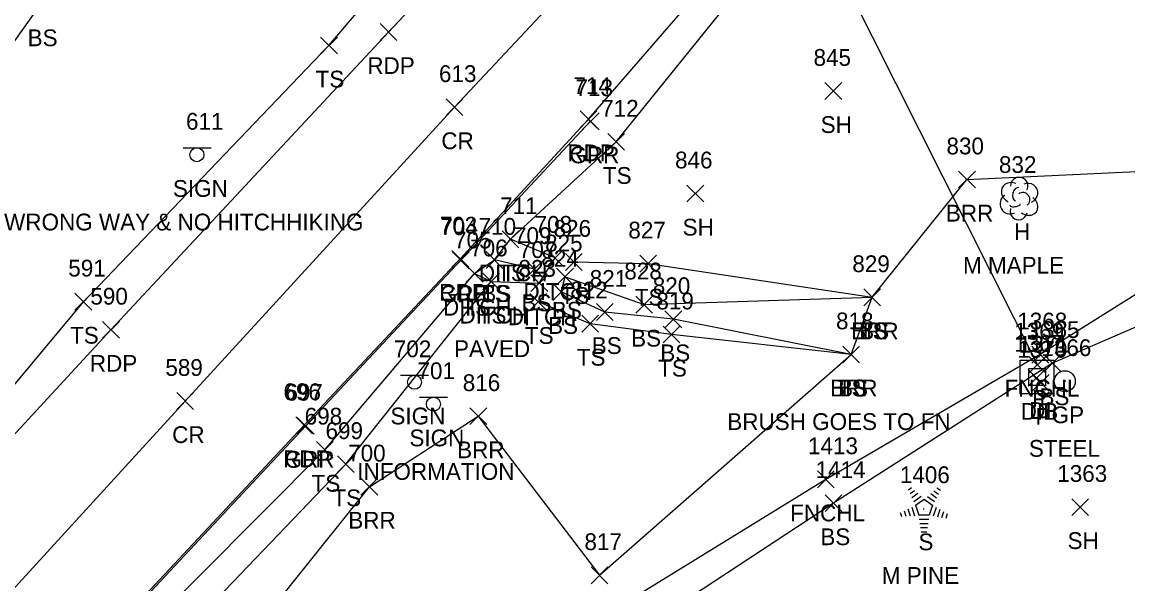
# Model space of a CAD drawing. Extents: x 1688195 to 1692013, y 424605 to 441234.
# Drawn here: x 1691586.4 to 1691718.1, y 439107.6 to 439174.5 of the extents above; entities that cross this region are included whole.
import ezdxf

# ---------------------------------------------------------------- set-up
doc = ezdxf.new("R2010")
doc.units = 0
for name, color, linetype in [('D_A', 7, 'Continuous'), ('D_C', 7, 'Continuous'), ('D_I', 7, 'Continuous'), ('D_TIC', 7, 'Continuous'), ('DCP', 7, 'Continuous'), ('DD', 7, 'Continuous'), ('DS', 7, 'Continuous'), ('L_A', 7, 'Continuous'), ('L_C', 7, 'Continuous'), ('L_I', 7, 'Continuous'), ('L_TIC', 7, 'Continuous'), ('LABL', 7, 'Continuous'), ('LELB', 7, 'Continuous'), ('LFNC', 7, 'Continuous'), ('LTC', 7, 'Continuous'), ('LTD', 7, 'Continuous'), ('P_A', 7, 'Continuous'), ('P_I', 7, 'Continuous'), ('P_TIC', 7, 'Continuous'), ('PET', 7, 'Continuous'), ('PRC', 7, 'Continuous'), ('R_A', 7, 'Continuous'), ('R_C', 7, 'Continuous'), ('R_I', 7, 'Continuous'), ('R_TIC', 7, 'Continuous'), ('RGP', 7, 'Continuous'), ('RGR', 7, 'Continuous'), ('S_A', 7, 'Continuous'), ('S_C', 7, 'Continuous'), ('S_I', 7, 'Continuous'), ('SSGN', 7, 'Continuous')]:
    doc.layers.add(name, color=color, linetype=linetype)

msp = doc.modelspace()

# ---------------------------------------------------------------- linework, layer by layer
at = {"layer": 'D_TIC'}
for points in [[(1691643.54, 439147.64), (1691645.54, 439149.64)], [(1691645.54, 439147.64), (1691643.54, 439149.64)], [(1691648.86, 439145.42), (1691650.86, 439147.42)], [(1691650.86, 439145.42), (1691648.86, 439147.42)], [(1691639.28, 439143.55), (1691641.28, 439145.55)], [(1691641.28, 439143.55), (1691639.28, 439145.55)], [(1691641.24, 439142.61), (1691643.24, 439144.61)], [(1691643.24, 439142.61), (1691641.24, 439144.61)], [(1691646.98, 439142.41), (1691648.98, 439144.41)], [(1691648.98, 439142.41), (1691646.98, 439144.41)], [(1691706.28, 439132.69), (1691708.28, 439134.69)], [(1691708.28, 439132.69), (1691706.28, 439134.69)], [(1691706.2, 439131.14), (1691708.2, 439133.14)], [(1691708.2, 439131.14), (1691706.2, 439133.14)], [(1691706.68, 439130.54), (1691708.68, 439132.54)], [(1691708.68, 439130.54), (1691706.68, 439132.54)]]:
    msp.add_lwpolyline(points, dxfattribs=at)
at = {"layer": 'DCP'}
msp.add_lwpolyline([(1691648.19, 439251.17), (1691707.28, 439133.69)], dxfattribs=at)
at = {"layer": 'DD'}
msp.add_lwpolyline([(1691640.28, 439144.55), (1691642.24, 439143.61), (1691647.98, 439143.41), (1691649.86, 439146.42), (1691644.54, 439148.64)], dxfattribs=at)
at = {"layer": 'DS'}
for p, q in [((1691705.25, 439134.24), (1691709.25, 439134.24)), ((1691705.25, 439130.24), (1691705.25, 439134.24)), ((1691709.25, 439134.24), (1691709.25, 439130.24)), ((1691706.25, 439131.24), (1691706.25, 439133.24)), ((1691706.25, 439133.24), (1691708.25, 439133.24)), ((1691707.26, 439132.24), (1691707.26, 439132.24)), ((1691707.26, 439132.24), (1691707.26, 439132.24)), ((1691708.25, 439133.24), (1691708.25, 439131.24)), ((1691708.25, 439131.24), (1691706.25, 439131.24)), ((1691709.25, 439130.24), (1691705.25, 439130.24))]:
    msp.add_line(p, q, dxfattribs=at)
at = {"layer": 'L_TIC'}
for points in [[(1691621.93, 439170.73), (1691623.93, 439172.73)], [(1691623.93, 439170.73), (1691621.93, 439172.73)], [(1691681.99, 439165.31), (1691683.99, 439167.31)], [(1691683.99, 439165.31), (1691681.99, 439167.31)], [(1691656.14, 439159.25), (1691658.14, 439161.25)], [(1691658.14, 439159.25), (1691656.14, 439161.25)], [(1691697.9, 439154.76), (1691699.9, 439156.76)], [(1691699.9, 439154.76), (1691697.9, 439156.76)], [(1691665.56, 439153.09), (1691667.56, 439155.09)], [(1691667.56, 439153.09), (1691665.56, 439155.09)], [(1691643.54, 439147.64), (1691645.54, 439149.64)], [(1691645.54, 439147.64), (1691643.54, 439149.64)], [(1691641.63, 439145.18), (1691643.63, 439147.18)], [(1691643.63, 439145.18), (1691641.63, 439147.18)], [(1691641.63, 439145.18), (1691643.63, 439147.18)], [(1691643.63, 439145.18), (1691641.63, 439147.18)], [(1691651.1, 439144.94), (1691653.1, 439146.94)], [(1691653.1, 439144.94), (1691651.1, 439146.94)], [(1691659.94, 439144.74), (1691661.94, 439146.74)], [(1691661.94, 439144.74), (1691659.94, 439146.74)], [(1691639.28, 439143.55), (1691641.28, 439145.55)], [(1691641.28, 439143.55), (1691639.28, 439145.55)], [(1691646.41, 439144.08), (1691648.41, 439146.08)], [(1691648.41, 439144.08), (1691646.41, 439146.08)], [(1691641.24, 439142.61), (1691643.24, 439144.61)], [(1691643.24, 439142.61), (1691641.24, 439144.61)], [(1691650.04, 439143.19), (1691652.04, 439145.19)], [(1691652.04, 439143.19), (1691650.04, 439145.19)], [(1691649.58, 439141.37), (1691651.58, 439143.37)], [(1691651.58, 439141.37), (1691649.58, 439143.37)], [(1691686.62, 439140.73), (1691688.62, 439142.73)], [(1691688.62, 439140.73), (1691686.62, 439142.73)], [(1691686.62, 439140.73), (1691688.62, 439142.73)], [(1691688.62, 439140.73), (1691686.62, 439142.73)], [(1691686.62, 439140.73), (1691688.62, 439142.73)], [(1691688.62, 439140.73), (1691686.62, 439142.73)], [(1691592.69, 439140.21), (1691594.69, 439142.21)], [(1691594.69, 439140.21), (1691592.69, 439142.21)], [(1691646.85, 439140.18), (1691648.85, 439142.18)], [(1691648.85, 439140.18), (1691646.85, 439142.18)], [(1691659.47, 439139.86), (1691661.47, 439141.86)], [(1691661.47, 439139.86), (1691659.47, 439141.86)], [(1691654.77, 439138.98), (1691656.77, 439140.98)], [(1691656.77, 439138.98), (1691654.77, 439140.98)], [(1691662.94, 439138.11), (1691664.94, 439140.11)], [(1691664.94, 439138.11), (1691662.94, 439140.11)], [(1691653.03, 439137.59), (1691655.03, 439139.59)], [(1691655.03, 439137.59), (1691653.03, 439139.59)], [(1691662.72, 439136.29), (1691664.72, 439138.29)], [(1691664.72, 439136.29), (1691662.72, 439138.29)], [(1691684.11, 439133.92), (1691686.11, 439135.92)], [(1691686.11, 439133.92), (1691684.11, 439135.92)], [(1691684.11, 439133.92), (1691686.11, 439135.92)], [(1691686.11, 439133.92), (1691684.11, 439135.92)], [(1691684.11, 439133.92), (1691686.11, 439135.92)], [(1691686.11, 439133.92), (1691684.11, 439135.92)], [(1691706.63, 439133.9), (1691708.63, 439135.9)], [(1691708.63, 439133.9), (1691706.63, 439135.9)], [(1691708.09, 439132.88), (1691710.09, 439134.88)], [(1691710.09, 439132.88), (1691708.09, 439134.88)], [(1691639.71, 439126.56), (1691641.71, 439128.56)], [(1691641.71, 439126.56), (1691639.71, 439128.56)], [(1691621.45, 439122.57), (1691623.45, 439124.57)], [(1691623.45, 439122.57), (1691621.45, 439124.57)], [(1691623.94, 439120.84), (1691625.94, 439122.84)], [(1691625.94, 439120.84), (1691623.94, 439122.84)], [(1691681.09, 439119.04), (1691683.09, 439121.04)], [(1691683.09, 439119.04), (1691681.09, 439121.04)], [(1691626.74, 439118.17), (1691628.74, 439120.17)], [(1691628.74, 439118.17), (1691626.74, 439120.17)], [(1691682, 439116.2), (1691684, 439118.2)], [(1691684, 439116.2), (1691682, 439118.2)], [(1691711.39, 439115.74), (1691713.39, 439117.74)], [(1691713.39, 439115.74), (1691711.39, 439117.74)], [(1691654.14, 439107.61), (1691656.14, 439109.61)], [(1691656.14, 439107.61), (1691654.14, 439109.61)]]:
    msp.add_lwpolyline(points, dxfattribs=at)
at = {"layer": 'LABL'}
msp.add_lwpolyline([(1691601.59, 439075.8), (1691600.49, 439085.06), (1691627.74, 439119.17), (1691640.71, 439127.56), (1691655.14, 439108.61), (1691685.11, 439134.92), (1691687.62, 439141.73), (1691698.9, 439155.76), (1691733.43, 439157.4), (1691776.41, 439186.57), (1691794.38, 439190.21)], dxfattribs=at)
at = {"layer": 'LELB'}
for points in [[(1691372.73, 438902.64), (1691398.57, 438929.63), (1691421.61, 438954.81), (1691450.5, 438984.08), (1691477.46, 439013.34), (1691508.26, 439046.52), (1691540.85, 439082.44), (1691568.31, 439110.72), (1691593.69, 439141.21), (1691622.93, 439171.73), (1691652.84, 439206.76), (1691674.71, 439229.19), (1691701.22, 439256.48), (1691710.89, 439279.75), (1691723.95, 439307.99), (1691712.17, 439332.07), (1691693.94, 439358.26), (1691684, 439373.02)], [(1691362.51, 438912.64), (1691386.93, 438940.67), (1691409.23, 438967.09), (1691436.47, 438996.99), (1691463, 439026.81), (1691492.43, 439060.22), (1691523.16, 439097.82), (1691549.35, 439125.66), (1691575.52, 439158.24), (1691588.61, 439176.65), (1691597.67, 439188.52), (1691599.59, 439192.01), (1691624.28, 439223.08), (1691646.72, 439249.94), (1691645.87, 439250.99)], [(1691494.97, 438989.23), (1691529.39, 439026.47), (1691563.11, 439061.46), (1691592.32, 439093.25), (1691622.45, 439123.57), (1691640.28, 439144.55), (1691642.63, 439146.18), (1691644.54, 439148.64), (1691657.14, 439160.25), (1691677.5, 439185.53), (1691687.79, 439198.06), (1691700.53, 439206.6), (1691711.71, 439214.4), (1691729.93, 439221), (1691765.22, 439228.65), (1691785.8, 439230.06)], [(1691867.08, 439165.21), (1691844.95, 439160.27), (1691798.84, 439152.11), (1691745.51, 439147.11), (1691728.71, 439142.4), (1691709.09, 439133.88), (1691683, 439117.2), (1691643.28, 439091.08), (1691604.89, 439061.29), (1691572.53, 439026.72), (1691542.38, 438995.55), (1691505.84, 438957.5), (1691487.66, 438936.34), (1691466.81, 438915.54), (1691436.02, 438880.86), (1691415.55, 438858.76)], [(1691647.41, 439145.08), (1691642.63, 439146.18)], [(1691652.1, 439145.94), (1691660.94, 439145.74), (1691687.62, 439141.73)], [(1691685.11, 439134.92), (1691663.94, 439139.11), (1691655.77, 439139.98), (1691650.58, 439142.37), (1691651.04, 439144.19), (1691660.47, 439140.86), (1691687.62, 439141.73)], [(1691497.62, 438986.55), (1691532.48, 439023.13), (1691565.52, 439059.1), (1691594.4, 439089.96), (1691624.94, 439121.84), (1691642.24, 439143.61)], [(1691685.11, 439134.92), (1691663.72, 439137.29), (1691654.03, 439138.59), (1691647.85, 439141.18)]]:
    msp.add_lwpolyline(points, dxfattribs=at)
at = {"layer": 'LFNC'}
msp.add_lwpolyline([(1691844.63, 439219.19), (1691827.3, 439208.18), (1691808.98, 439197.07), (1691805.18, 439194.78), (1691802.65, 439193.15), (1691780.93, 439179.95), (1691740.49, 439155.55), (1691707.63, 439134.9), (1691682.09, 439120.04), (1691638.96, 439093.47), (1691599.84, 439067.34), (1691566.38, 439033.38), (1691536.95, 439001.22), (1691500.89, 438961.26), (1691462.91, 438919.55), (1691429.39, 438883.14), (1691411.26, 438863.12)], dxfattribs=at)
at = {"layer": 'LTC'}
for p, q in [((1691691.93, 439118.8), (1691692.29, 439119.06)), ((1691695.33, 439119.04), (1691695.75, 439118.74)), ((1691692.14, 439118.34), (1691692.67, 439118.72)), ((1691692.35, 439117.87), (1691693.05, 439118.38)), ((1691692.56, 439117.4), (1691693.44, 439118.04)), ((1691692.78, 439116.95), (1691693.8, 439117.68)), ((1691693.8, 439117.68), (1691694.79, 439116.96)), ((1691694.22, 439118), (1691695.03, 439117.41)), ((1691694.59, 439118.35), (1691695.27, 439117.85)), ((1691694.96, 439118.69), (1691695.51, 439118.29)), ((1691691.87, 439116.51), (1691692.15, 439115.68)), ((1691692.33, 439116.73), (1691692.66, 439115.71)), ((1691692.78, 439116.95), (1691693.17, 439115.76)), ((1691694.79, 439116.96), (1691694.4, 439115.76)), ((1691695.23, 439116.69), (1691694.89, 439115.65)), ((1691695.68, 439116.44), (1691695.39, 439115.55)), ((1691690.96, 439116.08), (1691691.12, 439115.61)), ((1691691.42, 439116.3), (1691691.63, 439115.65)), ((1691694.4, 439115.76), (1691693.17, 439115.76)), ((1691694.36, 439115.26), (1691693.22, 439115.26)), ((1691696.12, 439116.19), (1691695.88, 439115.46)), ((1691696.56, 439115.94), (1691696.38, 439115.36)), ((1691694.28, 439114.76), (1691693.29, 439114.76)), ((1691694.2, 439114.26), (1691693.36, 439114.26)), ((1691694.11, 439113.76), (1691693.44, 439113.76))]:
    msp.add_line(p, q, dxfattribs=at)
at = {"layer": 'LTD'}
msp.add_line((1691705.07, 439153.55), (1691705.07, 439153.55), dxfattribs=at)
msp.add_line((1691705.07, 439153.55), (1691705.07, 439153.55), dxfattribs=at)
msp.add_arc((1691705.12, 439154.98), 1.05, 335.5272, 180.9563, dxfattribs=at)
for centre, major_axis, ratio, start_param, end_param in [((1691704.28, 439154.21), (1.21, -0.51), 0.895232, 1.570796, 4.712389), ((1691704.87, 439154.01), (-0.208, -0.792), 0.645439, 3.141593, 6.283185), ((1691706.11, 439154.13), (-1.14, -0.48), 0.949671, 1.570796, 4.712389), ((1691703.99, 439152.84), (0.58, -1.04), 0.959034, 3.141593, 6.283185), ((1691705.57, 439153.38), (-0.5, 0.667), 0.989748, 3.141593, 6.283185), ((1691706.07, 439152.71), (-1.09, 0.79), 0.841452, 1.570796, 4.712389), ((1691705.07, 439152.05), (0.26, 1.06), 0.942809, 1.570796, 4.712389), ((1691704.62, 439152.8), (-0.625, -0.083), 0.423636, 0, 3.141593)]:
    msp.add_ellipse(centre, major_axis=major_axis, ratio=ratio, start_param=start_param, end_param=end_param, dxfattribs=at)
at = {"layer": 'P_TIC'}
for points in [[(1691629.02, 439172.34), (1691631.02, 439174.34)], [(1691631.02, 439172.34), (1691629.02, 439174.34)], [(1691636.88, 439163.38), (1691638.88, 439165.38)], [(1691638.88, 439163.38), (1691636.88, 439165.38)], [(1691652.83, 439161.94), (1691654.83, 439163.94)], [(1691654.83, 439161.94), (1691652.83, 439163.94)], [(1691637.57, 439145.32), (1691639.57, 439147.32)], [(1691639.57, 439145.32), (1691637.57, 439147.32)], [(1691595.97, 439136.86), (1691597.97, 439138.86)], [(1691597.97, 439136.86), (1691595.97, 439138.86)], [(1691604.82, 439128.37), (1691606.82, 439130.37)], [(1691606.82, 439128.37), (1691604.82, 439130.37)], [(1691618.98, 439125.48), (1691620.98, 439127.48)], [(1691620.98, 439125.48), (1691618.98, 439127.48)]]:
    msp.add_lwpolyline(points, dxfattribs=at)
at = {"layer": 'PET'}
for points in [[(1691375.46, 438899.9), (1691401.5, 438927.23), (1691424.19, 438951.44), (1691479.53, 439011.25), (1691510.32, 439044.28), (1691543.27, 439079.53), (1691570.24, 439108.89), (1691596.97, 439137.86), (1691630.02, 439173.34), (1691657.32, 439202.46), (1691678.85, 439225.99), (1691705.09, 439253.29), (1691720.65, 439270.18), (1691741.75, 439292.31), (1691750.04, 439301.33), (1691750.82, 439305.81), (1691750.97, 439309.53)], [(1691527.98, 439028.02), (1691561.01, 439063.43), (1691590.68, 439095.16), (1691619.98, 439126.48), (1691638.57, 439146.32), (1691653.83, 439162.94), (1691673.33, 439185.49), (1691673.65, 439189.01), (1691685.04, 439200.74), (1691697.53, 439210.68), (1691709.71, 439218.34), (1691715.71, 439221.67), (1691737.08, 439230.06)]]:
    msp.add_lwpolyline(points, dxfattribs=at)
at = {"layer": 'PRC'}
msp.add_lwpolyline([(1691383.45, 438891.46), (1691410.11, 438918.45), (1691432.71, 438943.44), (1691460.69, 438973.59), (1691487.77, 439002.58), (1691519.39, 439036.11), (1691551.83, 439070.88), (1691579.21, 439100.29), (1691605.82, 439129.37), (1691637.88, 439164.38), (1691665.6, 439193.96), (1691687.96, 439216.92), (1691714.01, 439245.27), (1691730.35, 439261.96), (1691750.53, 439284.62), (1691763.38, 439297.71)], dxfattribs=at)
at = {"layer": 'R_TIC'}
for points in [[(1691653.09, 439161.7), (1691655.09, 439163.7)], [(1691655.09, 439161.7), (1691653.09, 439163.7)], [(1691637.64, 439145.14), (1691639.64, 439147.14)], [(1691639.64, 439145.14), (1691637.64, 439147.14)], [(1691619.16, 439125.42), (1691621.16, 439127.42)], [(1691621.16, 439125.42), (1691619.16, 439127.42)]]:
    msp.add_lwpolyline(points, dxfattribs=at)
at = {"layer": 'RGP'}
msp.add_line((1691710.55, 439131.73), (1691710.55, 439131.73), dxfattribs=at)
for radius in [1.25, 0.0833]:
    msp.add_circle((1691710.55, 439131.73), radius, dxfattribs=at)
at = {"layer": 'RGR'}
msp.add_lwpolyline([(1691392.43, 438882.91), (1691415.63, 438907.66), (1691443.42, 438937.01), (1691473.56, 438969.15), (1691494.4, 438991.79), (1691528.19, 439027.86), (1691561.17, 439063.3), (1691590.77, 439094.95), (1691620.16, 439126.42), (1691638.64, 439146.14), (1691654.09, 439162.7)], dxfattribs=at)
at = {"layer": 'SSGN'}
for p, q in [((1691605.56, 439159.55), (1691608.89, 439159.55)), ((1691607.21, 439158.72), (1691607.21, 439158.72)), ((1691631.46, 439132.45), (1691634.79, 439132.45)), ((1691633.11, 439131.61), (1691633.11, 439131.61)), ((1691633.72, 439129.83), (1691637.05, 439129.83)), ((1691635.37, 439129), (1691635.37, 439129))]:
    msp.add_line(p, q, dxfattribs=at)
for centre in [(1691607.21, 439158.72), (1691633.11, 439131.61), (1691635.37, 439129)]:
    msp.add_circle(centre, 0.833, dxfattribs=at)

# ---------------------------------------------------------------- texts
at = {"layer": 'D_A'}
for s, p in [('DITCH', (1691640.78, 439143.64)), ('DITCH', (1691646.09, 439141.42)), ('DITCH', (1691636.51, 439139.55)), ('DITCH', (1691638.47, 439138.61)), ('DITCH', (1691644.22, 439138.41)), ('P', (1691706.66, 439128.69)), ('DIB', (1691705.3, 439127.14)), ('DI', (1691706.31, 439127.24)), ('P', (1691707.05, 439126.54))]:
    msp.add_text(s, height=2, dxfattribs=at).set_placement(p)
at = {"layer": 'D_C'}
msp.add_text('PAVED', height=2, dxfattribs=at).set_placement((1691637.82, 439134.61))
at = {"layer": 'D_I'}
for s, p in [('711', (1691643.31, 439151.64)), ('708', (1691647.42, 439149.42)), ('705', (1691637.83, 439147.55)), ('706', (1691639.74, 439146.61)), ('707', (1691645.54, 439146.41)), ('1369', (1691704.53, 439136.69)), ('1367', (1691704.52, 439135.24)), ('1370', (1691704.9, 439134.54)), ('1371', (1691705.07, 439135.14))]:
    msp.add_text(s, height=2, dxfattribs=at).set_placement(p)
at = {"layer": 'L_A'}
for s, p in [('BS', (1691587.05, 439171.65)), ('TS', (1691621.34, 439166.73)), ('SH', (1691681.48, 439161.31)), ('TS', (1691655.55, 439155.25)), ('BRR', (1691696.39, 439150.76)), ('SH', (1691665.04, 439149.09)), ('H', (1691704.51, 439148.55)), ('TS', (1691642.95, 439143.64)), ('TS', (1691641.04, 439141.18)), ('BS', (1691641.07, 439141.18)), ('TS', (1691650.51, 439140.94)), ('TS', (1691659.35, 439140.74)), ('TS', (1691638.69, 439139.55)), ('BS', (1691645.85, 439140.08)), ('TS', (1691640.65, 439138.61)), ('BS', (1691649.48, 439139.19)), ('BS', (1691649.02, 439137.37)), ('BRR', (1691685.11, 439136.73)), ('TS', (1691686.03, 439136.73)), ('BS', (1691686.06, 439136.73)), ('TS', (1691592.1, 439136.21)), ('TS', (1691646.26, 439136.18)), ('BS', (1691658.91, 439135.86)), ('BS', (1691654.22, 439134.98)), ('BS', (1691662.38, 439134.11)), ('TS', (1691652.44, 439133.59)), ('TS', (1691662.13, 439132.29)), ('BRR', (1691682.6, 439129.92)), ('TS', (1691683.52, 439129.92)), ('BS', (1691683.55, 439129.92)), ('FNCHL', (1691703.38, 439129.9)), ('BS', (1691707.53, 439128.88)), ('BRR', (1691638.19, 439122.56)), ('TS', (1691620.86, 439118.57)), ('TS', (1691623.35, 439116.84)), ('FNCHL', (1691677.84, 439115.04)), ('BRR', (1691625.23, 439114.17)), ('BS', (1691681.44, 439112.2)), ('SH', (1691710.88, 439111.74)), ('S', (1691693.12, 439111.59))]:
    msp.add_text(s, height=2, dxfattribs=at).set_placement(p)
at = {"layer": 'L_C'}
for s, p in [('M MAPLE', (1691698.43, 439144.55)), ('BRUSH GOES TO FN', (1691670.36, 439125.92)), ('M PINE', (1691688.76, 439107.59))]:
    msp.add_text(s, height=2, dxfattribs=at).set_placement(p)
at = {"layer": 'L_I'}
for s, p in [('845', (1691680.63, 439169.31)), ('712', (1691655.34, 439163.25)), ('830', (1691696.46, 439158.76)), ('846', (1691664.14, 439157.09)), ('832', (1691702.71, 439156.55)), ('711', (1691643.31, 439151.64)), ('710', (1691640.75, 439149.18)), ('710', (1691640.75, 439149.18)), ('826', (1691649.68, 439148.94)), ('827', (1691658.58, 439148.74)), ('705', (1691637.83, 439147.55)), ('709', (1691644.96, 439148.08)), ('706', (1691639.74, 439146.61)), ('825', (1691648.67, 439147.19)), ('824', (1691648.22, 439145.37)), ('829', (1691685.25, 439144.73)), ('829', (1691685.25, 439144.73)), ('829', (1691685.25, 439144.73)), ('591', (1691591.89, 439144.21)), ('823', (1691645.49, 439144.18)), ('828', (1691658.1, 439143.86)), ('821', (1691653.98, 439142.98)), ('820', (1691661.49, 439142.11)), ('822', (1691651.67, 439141.59)), ('819', (1691661.92, 439140.29)), ('818', (1691683.31, 439137.92)), ('818', (1691683.31, 439137.92)), ('818', (1691683.31, 439137.92)), ('1368', (1691704.89, 439137.9)), ('1365', (1691706.35, 439136.88)), ('816', (1691638.86, 439130.56)), ('698', (1691620.04, 439126.57)), ('699', (1691622.52, 439124.84)), ('1413', (1691679.97, 439123.04)), ('700', (1691625.22, 439122.17)), ('1414', (1691680.87, 439120.2)), ('1406', (1691690.91, 439119.59)), ('1363', (1691709.65, 439119.74)), ('817', (1691653.35, 439111.61))]:
    msp.add_text(s, height=2, dxfattribs=at).set_placement(p)
at = {"layer": 'LTC'}
msp.add_text('.', height=1.04, rotation=270, dxfattribs=at).set_placement((1691693.68, 439116.7))
at = {"layer": 'P_A'}
for s, p in [('RDP', (1691627.5, 439168.34)), ('CR', (1691636.31, 439159.38)), ('RDP', (1691651.32, 439157.94)), ('RDP', (1691636.06, 439141.32)), ('RDP', (1691594.46, 439132.86)), ('CR', (1691604.26, 439124.37)), ('RDP', (1691617.46, 439121.48))]:
    msp.add_text(s, height=2, dxfattribs=at).set_placement(p)
at = {"layer": 'P_I'}
for s, p in [('613', (1691636.03, 439167.38)), ('714', (1691652.04, 439165.94)), ('703', (1691636.13, 439149.32)), ('590', (1691594.52, 439140.86)), ('589', (1691603.45, 439132.37)), ('696', (1691617.51, 439129.48))]:
    msp.add_text(s, height=2, dxfattribs=at).set_placement(p)
at = {"layer": 'R_A'}
for s, p in [('GRR', (1691651.57, 439157.7)), ('GRR', (1691636.13, 439141.14)), ('GP', (1691708.98, 439126.73)), ('GRR', (1691617.65, 439121.42))]:
    msp.add_text(s, height=2, dxfattribs=at).set_placement(p)
at = {"layer": 'R_C'}
msp.add_text('STEEL', height=2, dxfattribs=at).set_placement((1691706.27, 439122.73))
at = {"layer": 'R_I'}
for s, p in [('713', (1691652.29, 439165.7)), ('704', (1691636.2, 439149.14)), ('1366', (1691707.76, 439134.73)), ('697', (1691617.75, 439129.42))]:
    msp.add_text(s, height=2, dxfattribs=at).set_placement(p)
at = {"layer": 'S_A'}
for p in [(1691604.35, 439153.7), (1691630.25, 439126.59), (1691632.51, 439123.98)]:
    msp.add_text('SIGN', height=2, dxfattribs=at).set_placement(p)
at = {"layer": 'S_C'}
for s, p in [('WRONG WAY & NO HITCHHIKING', (1691584.25, 439149.7)), ('INFORMATION', (1691626.3, 439119.98))]:
    msp.add_text(s, height=2, dxfattribs=at).set_placement(p)
at = {"layer": 'S_I'}
for s, p in [('611', (1691605.91, 439161.7)), ('702', (1691630.65, 439134.59)), ('701', (1691633.47, 439131.98))]:
    msp.add_text(s, height=2, dxfattribs=at).set_placement(p)

doc.saveas('drawing.dxf')
